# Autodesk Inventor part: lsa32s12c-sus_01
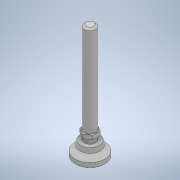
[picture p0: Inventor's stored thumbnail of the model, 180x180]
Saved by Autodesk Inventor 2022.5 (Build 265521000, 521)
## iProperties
Part Number: lsa32s12c-sus_01
Material: 一般
Document SubType Name: Modeling
Designer: ImaoCorp
Density: 1 g/cm^3
Appearance: 既定
Author: ImaoCorp
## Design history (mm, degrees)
feature "lsa32s12c-sus_01"
node "ソリッド1"
